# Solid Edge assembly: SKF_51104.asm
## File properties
Title: SKF_51104
Author: psAdmin
Comments: Thrust ball bearings, single direction
Template: iso metric assembly.asm
Last saved by: morva
Revision: 3
Application: Solid Edge
Username: psAdmin
Document Number: SKF_51104
Company: SKF
NB: SKF_51104
NN: BD1_001_BDC_001
NT: Thrust ball bearings, single direction
NBSYN: SKF_$TC.
LINA: SKF_51104
CATALOG: SKF
DESIGNATION: 51104
WASHER: No seat washer
DD: 20.0
D: 35.0
H: 10.00
LOAD1: 15.1
LOAD2: 29.0
LOAD3: 1.1
SPEED1: 7500
SPEED2: 10000
BEARING: 51104
SUPPLIER: SKF
ARTICLENO: SKF_51104
BOMINFO: SKF_51104
CREATOR: CADENAS GmbH
ID: skf:SKF_51104
CADENASIDSTR: DOCATTR{IDENT{"{$CADENAS_DATA/23d-libs/skf/bearings_units_and_housings/ball_bearings/thrust_ball_bearings/bd1_001_bdc_001.prj},176 {VTYP=3D},{NB=SKF_51104},{LINA=SKF_51104},{NN=BD1_001_BDC_001},{DATE=08.09.2023 08:50:36},{GEOMDATE=04.09.2023 08:34:44},{VERSION=},{LINEID=46530},{WBVAR=WASHER},{WBNUMERIC=}  {NB=SKF_51104},{LINA=SKF_51104},{KT=DUMMY},{DESIGNATION=51104},{WASHER=},{DD=20.0},{D=35.0},{DX=},{DXX=MIN},{H=10.00},{H1=},{DD1=35.00},{D1=21.00},{D2=},{D3=},{C=},{R=},{SS=},{R12=0.3},{PITCH=27.500},{DW=5.556},{ALPHA=90},{DAMIN=29.00},{DAMAX=26.00},{RAMAX=0.30},{LOAD1=15.1},{LOAD2=29.0},{LOAD3=1.1},{SPEED1=7500},{SPEED2=10000},{A=0.0044},{Z=14},{II=1},{MASS=0.03700},{BEARING=51104},{WASHERVAR=},{POPULAR=Yes},{XHO=7.2224},{BHO=2.7776},{BSH=2.7776},{Y3=0},{H3=0},{B3=0},{WASHERALG='','No seat washer'},{WSPN=},{DESIGN=tbb1},{H1ALG=0},{SSALG=0},{RALG=0},{TC=51104},{DXA=35.000}"}}
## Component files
SKF_51104_PART1.par
SKF_51104_PART2.par
SKF_51104_PART3.par
SKF_51104_PART4.par
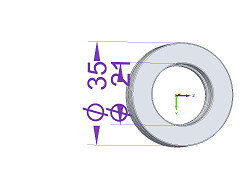
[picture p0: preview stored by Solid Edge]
